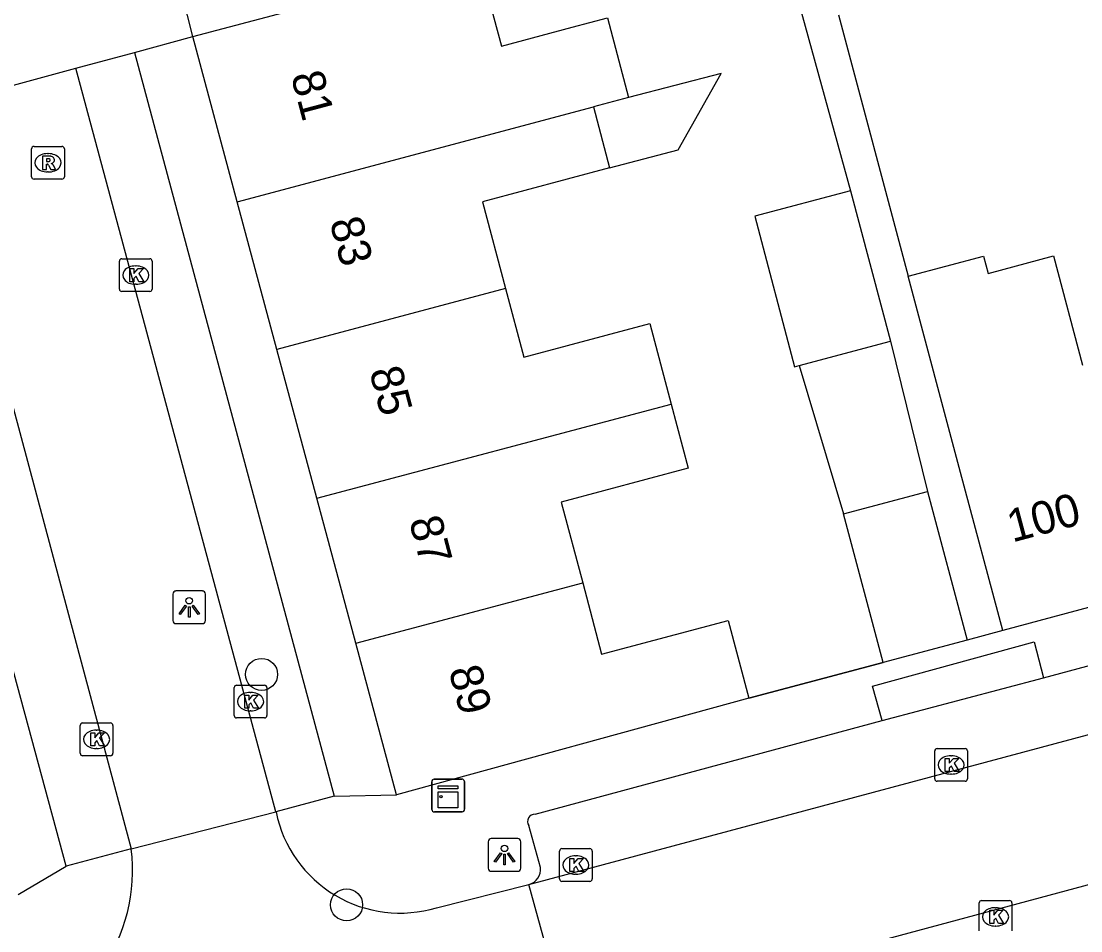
# Model space of a CAD drawing. Extents: x 162542 to 163144, y 380786 to 381511.
# Drawn here: x 162798.21 to 162830.58, y 381069.57 to 381097.35 of the extents above; entities that cross this region are included whole.
import ezdxf

# ---------------------------------------------------------------- set-up
doc = ezdxf.new("R2010")
doc.units = 0
for name, color, linetype in [('IMGEO_Boom', 7, 'Continuous'), ('IMGEO_Kast', 7, 'Continuous'), ('IMGEO_Kolk', 7, 'Continuous'), ('IMGEO_Lichtpunt', 7, 'Continuous'), ('IMGEO_Muur', 7, 'Continuous'), ('IMGEO_Pand', 7, 'Continuous'), ('IMGEO_Pand_nummerreeks', 7, 'Continuous'), ('IMGEO_Rijbaan_lokaal_open', 7, 'Continuous'), ('IMGEO_Rioolput', 7, 'Continuous'), ('IMGEO_Voetpad_open', 7, 'Continuous')]:
    doc.layers.add(name, color=color, linetype=linetype)

msp = doc.modelspace()

# ---------------------------------------------------------------- linework, layer by layer
at = {"layer": 'IMGEO_Boom'}
for centre in [(162805.552, 381077.403), (162808.149, 381070.365)]:
    msp.add_circle(centre, 0.489, dxfattribs=at)
at = {"layer": 'IMGEO_Kast'}
for p, q in [((162810.751, 381073.279), (162810.751, 381074.12)), ((162810.751, 381074.12), (162810.751, 381073.279)), ((162810.826, 381074.204), (162811.667, 381074.204)), ((162811.667, 381074.204), (162810.826, 381074.204)), ((162811.751, 381074.129), (162811.751, 381073.288)), ((162811.751, 381073.288), (162811.751, 381074.129)), ((162811.676, 381073.204), (162810.835, 381073.204)), ((162810.835, 381073.204), (162811.676, 381073.204))]:
    msp.add_line(p, q, dxfattribs=at)
for points in [[(162810.946, 381073.994), (162811.546, 381073.994), (162811.546, 381073.909), (162810.946, 381073.909), (162810.946, 381073.994)], [(162810.946, 381073.819), (162811.546, 381073.819), (162811.546, 381073.33), (162810.946, 381073.33), (162810.946, 381073.819)]]:
    msp.add_lwpolyline(points, dxfattribs=at)
msp.add_circle((162811.03, 381073.668), 0.0377, dxfattribs=at)
for centre, start, end in [((162810.829, 381074.126), 92.4484, 184.2845), ((162810.829, 381074.126), 92.4484, 184.2845), ((162811.673, 381074.126), 2.4484, 94.2845), ((162811.673, 381074.126), 2.4484, 94.2845), ((162810.829, 381073.282), 182.4484, 274.2845), ((162810.829, 381073.282), 182.4484, 274.2845), ((162811.673, 381073.282), 272.4484, 4.2845), ((162811.673, 381073.282), 272.4484, 4.2845)]:
    msp.add_arc(centre, 0.0779, start, end, dxfattribs=at)
at = {"layer": 'IMGEO_Kolk'}
for p, q in [((162801.208, 381089.169), (162801.208, 381090.021)), ((162801.283, 381090.095), (162802.135, 381090.095)), ((162802.209, 381090.021), (162802.209, 381089.169)), ((162801.696, 381089.875), (162801.721, 381089.875)), ((162802.135, 381089.095), (162801.283, 381089.095)), ((162801.719, 381089.315), (162801.694, 381089.315)), ((162804.789, 381077.071), (162805.641, 381077.071)), ((162804.714, 381076.145), (162804.714, 381076.997)), ((162805.202, 381076.851), (162805.227, 381076.851)), ((162805.715, 381076.997), (162805.715, 381076.145)), ((162805.641, 381076.071), (162804.789, 381076.071)), ((162805.225, 381076.291), (162805.2, 381076.291)), ((162800.01, 381074.992), (162800.01, 381075.844)), ((162800.085, 381075.918), (162800.937, 381075.918)), ((162801.011, 381075.844), (162801.011, 381074.992)), ((162800.498, 381075.698), (162800.523, 381075.698)), ((162800.521, 381075.138), (162800.496, 381075.138)), ((162826.191, 381075.138), (162827.043, 381075.138)), ((162800.937, 381074.918), (162800.085, 381074.918)), ((162826.116, 381074.212), (162826.116, 381075.064)), ((162826.604, 381074.918), (162826.629, 381074.918)), ((162827.117, 381075.064), (162827.117, 381074.212)), ((162827.043, 381074.138), (162826.191, 381074.138)), ((162826.627, 381074.358), (162826.602, 381074.358)), ((162814.651, 381071.155), (162814.651, 381072.007)), ((162814.726, 381072.081), (162815.578, 381072.081)), ((162815.139, 381071.861), (162815.164, 381071.861)), ((162815.652, 381072.007), (162815.652, 381071.155)), ((162815.162, 381071.301), (162815.137, 381071.301)), ((162815.578, 381071.081), (162814.726, 381071.081)), ((162827.473, 381069.572), (162827.473, 381070.424)), ((162827.548, 381070.498), (162828.4, 381070.498)), ((162827.961, 381070.278), (162827.986, 381070.278)), ((162828.474, 381070.424), (162828.474, 381069.572)), ((162827.984, 381069.718), (162827.959, 381069.718))]:
    msp.add_line(p, q, dxfattribs=at)
for points in [[(162801.208, 381089.169), (162801.208, 381090.021)], [(162801.283, 381090.095), (162802.135, 381090.095)], [(162802.209, 381090.021), (162802.209, 381089.169)], [(162801.529, 381089.795), (162801.652, 381089.795), (162801.652, 381089.644), (162801.782, 381089.795), (162801.946, 381089.795), (162801.8, 381089.644), (162801.953, 381089.395), (162801.801, 381089.395), (162801.716, 381089.559), (162801.652, 381089.492), (162801.652, 381089.395), (162801.529, 381089.395), (162801.529, 381089.795)], [(162802.135, 381089.095), (162801.283, 381089.095)], [(162804.789, 381077.071), (162805.641, 381077.071)], [(162804.714, 381076.145), (162804.714, 381076.997)], [(162805.035, 381076.771), (162805.158, 381076.771), (162805.158, 381076.62), (162805.288, 381076.771), (162805.452, 381076.771), (162805.306, 381076.62), (162805.459, 381076.371), (162805.307, 381076.371), (162805.222, 381076.535), (162805.158, 381076.468), (162805.158, 381076.371), (162805.035, 381076.371), (162805.035, 381076.771)], [(162805.715, 381076.997), (162805.715, 381076.145)], [(162805.641, 381076.071), (162804.789, 381076.071)], [(162800.01, 381074.992), (162800.01, 381075.844)], [(162800.085, 381075.918), (162800.937, 381075.918)], [(162801.011, 381075.844), (162801.011, 381074.992)], [(162800.331, 381075.618), (162800.454, 381075.618), (162800.454, 381075.467), (162800.584, 381075.618), (162800.748, 381075.618), (162800.602, 381075.467), (162800.755, 381075.218), (162800.603, 381075.218), (162800.518, 381075.382), (162800.454, 381075.315), (162800.454, 381075.218), (162800.331, 381075.218), (162800.331, 381075.618)], [(162826.191, 381075.138), (162827.043, 381075.138)], [(162800.937, 381074.918), (162800.085, 381074.918)], [(162826.116, 381074.212), (162826.116, 381075.064)], [(162826.437, 381074.838), (162826.56, 381074.838), (162826.56, 381074.687), (162826.69, 381074.838), (162826.854, 381074.838), (162826.708, 381074.687), (162826.861, 381074.438), (162826.709, 381074.438), (162826.624, 381074.602), (162826.56, 381074.535), (162826.56, 381074.438), (162826.437, 381074.438), (162826.437, 381074.838)], [(162827.117, 381075.064), (162827.117, 381074.212)], [(162827.043, 381074.138), (162826.191, 381074.138)], [(162814.651, 381071.155), (162814.651, 381072.007)], [(162814.726, 381072.081), (162815.578, 381072.081)], [(162815.652, 381072.007), (162815.652, 381071.155)], [(162814.972, 381071.781), (162815.095, 381071.781), (162815.095, 381071.63), (162815.225, 381071.781), (162815.389, 381071.781), (162815.243, 381071.63), (162815.396, 381071.381), (162815.244, 381071.381), (162815.159, 381071.545), (162815.095, 381071.478), (162815.095, 381071.381), (162814.972, 381071.381), (162814.972, 381071.781)], [(162815.578, 381071.081), (162814.726, 381071.081)], [(162827.473, 381069.572), (162827.473, 381070.424)], [(162827.548, 381070.498), (162828.4, 381070.498)], [(162828.474, 381070.424), (162828.474, 381069.572)], [(162827.794, 381070.198), (162827.917, 381070.198), (162827.917, 381070.047), (162828.047, 381070.198), (162828.211, 381070.198), (162828.065, 381070.047), (162828.218, 381069.798), (162828.066, 381069.798), (162827.981, 381069.962), (162827.917, 381069.895), (162827.917, 381069.798), (162827.794, 381069.798), (162827.794, 381070.198)]]:
    msp.add_lwpolyline(points, dxfattribs=at)
for centre, start, end in [((162801.285, 381090.019), 91.552, 178.448), ((162801.285, 381090.019), 91.552, 178.448), ((162802.133, 381090.019), 1.552, 88.448), ((162802.133, 381090.019), 1.552, 88.448), ((162801.285, 381089.171), 181.552, 268.448), ((162801.285, 381089.171), 181.552, 268.448), ((162802.133, 381089.171), 271.552, 358.448), ((162802.133, 381089.171), 271.552, 358.448), ((162804.791, 381076.995), 91.552, 178.448), ((162804.791, 381076.995), 91.552, 178.448), ((162805.639, 381076.995), 1.552, 88.448), ((162805.639, 381076.995), 1.552, 88.448), ((162804.791, 381076.147), 181.552, 268.448), ((162804.791, 381076.147), 181.552, 268.448), ((162805.639, 381076.147), 271.552, 358.448), ((162805.639, 381076.147), 271.552, 358.448), ((162800.087, 381075.842), 91.552, 178.448), ((162800.087, 381075.842), 91.552, 178.448), ((162800.935, 381075.842), 1.552, 88.448), ((162800.935, 381075.842), 1.552, 88.448), ((162826.193, 381075.062), 91.552, 178.448), ((162826.193, 381075.062), 91.552, 178.448), ((162827.041, 381075.062), 1.552, 88.448), ((162827.041, 381075.062), 1.552, 88.448), ((162800.087, 381074.994), 181.552, 268.448), ((162800.087, 381074.994), 181.552, 268.448), ((162800.935, 381074.994), 271.552, 358.448), ((162800.935, 381074.994), 271.552, 358.448), ((162826.193, 381074.214), 181.552, 268.448), ((162826.193, 381074.214), 181.552, 268.448), ((162827.041, 381074.214), 271.552, 358.448), ((162827.041, 381074.214), 271.552, 358.448), ((162814.728, 381072.005), 91.552, 178.448), ((162814.728, 381072.005), 91.552, 178.448), ((162815.576, 381072.005), 1.552, 88.448), ((162815.576, 381072.005), 1.552, 88.448), ((162814.728, 381071.157), 181.552, 268.448), ((162814.728, 381071.157), 181.552, 268.448), ((162815.576, 381071.157), 271.552, 358.448), ((162815.576, 381071.157), 271.552, 358.448), ((162827.55, 381070.422), 91.552, 178.448), ((162827.55, 381070.422), 91.552, 178.448), ((162828.398, 381070.422), 1.552, 88.448), ((162828.398, 381070.422), 1.552, 88.448)]:
    msp.add_arc(centre, 0.0765, start, end, dxfattribs=at)
for centre, major_axis, ratio, start_param, end_param in [((162801.695, 381089.595), (-0.387, 0.002), 0.722429, 4.712389, 7.853982), ((162801.72, 381089.595), (-0.39, 0.002), 0.717154, 1.570796, 4.712389), ((162805.201, 381076.571), (-0.387, 0.002), 0.722429, 4.712389, 7.853982), ((162805.226, 381076.571), (-0.39, 0.002), 0.717154, 1.570796, 4.712389), ((162800.497, 381075.418), (-0.387, 0.002), 0.722429, 4.712389, 7.853982), ((162800.522, 381075.418), (-0.39, 0.002), 0.717154, 1.570796, 4.712389), ((162826.603, 381074.638), (-0.387, 0.002), 0.722429, 4.712389, 7.853982), ((162826.628, 381074.638), (-0.39, 0.002), 0.717154, 1.570796, 4.712389), ((162815.138, 381071.581), (-0.387, 0.002), 0.722429, 4.712389, 7.853982), ((162815.163, 381071.581), (-0.39, 0.002), 0.717154, 1.570796, 4.712389), ((162827.96, 381069.998), (-0.387, 0.002), 0.722429, 4.712389, 7.853982), ((162827.985, 381069.998), (-0.39, 0.002), 0.717154, 1.570796, 4.712389)]:
    msp.add_ellipse(centre, major_axis=major_axis, ratio=ratio, start_param=start_param, end_param=end_param, dxfattribs=at)
at = {"layer": 'IMGEO_Lichtpunt'}
for p, q in [((162803.744, 381079.949), (162802.936, 381079.949)), ((162803.744, 381079.949), (162802.936, 381079.949)), ((162802.842, 381079.854), (162802.842, 381079.047)), ((162802.842, 381079.854), (162802.842, 381079.047)), ((162803.838, 381079.047), (162803.838, 381079.854)), ((162803.838, 381079.047), (162803.838, 381079.854)), ((162802.936, 381078.953), (162803.744, 381078.953)), ((162802.936, 381078.953), (162803.744, 381078.953)), ((162812.475, 381072.292), (162812.475, 381071.485)), ((162812.475, 381072.292), (162812.475, 381071.485)), ((162813.377, 381072.387), (162812.569, 381072.387)), ((162813.377, 381072.387), (162812.569, 381072.387)), ((162813.471, 381071.485), (162813.471, 381072.292)), ((162813.471, 381071.485), (162813.471, 381072.292)), ((162812.569, 381071.391), (162813.377, 381071.391)), ((162812.569, 381071.391), (162813.377, 381071.391))]:
    msp.add_line(p, q, dxfattribs=at)
for points in [[(162803.216, 381079.518), (162803.255, 381079.49), (162803.067, 381079.228), (162803.029, 381079.255), (162803.216, 381079.518)], [(162803.318, 381079.47), (162803.365, 381079.47), (162803.365, 381079.148), (162803.318, 381079.148), (162803.318, 381079.47)], [(162803.428, 381079.49), (162803.466, 381079.517), (162803.653, 381079.255), (162803.614, 381079.227), (162803.428, 381079.49)], [(162812.849, 381071.956), (162812.888, 381071.928), (162812.7, 381071.666), (162812.662, 381071.693), (162812.849, 381071.956)], [(162812.951, 381071.908), (162812.998, 381071.908), (162812.998, 381071.586), (162812.951, 381071.586), (162812.951, 381071.908)], [(162813.061, 381071.928), (162813.099, 381071.955), (162813.286, 381071.693), (162813.247, 381071.665), (162813.061, 381071.928)]]:
    msp.add_lwpolyline(points, dxfattribs=at)
for centre in [(162803.341, 381079.652), (162812.974, 381072.09)]:
    msp.add_circle(centre, 0.0994, dxfattribs=at)
for centre, start, end in [((162802.936, 381079.854), 90, 180), ((162802.936, 381079.854), 90, 180), ((162803.744, 381079.854), 0, 90), ((162803.744, 381079.854), 0, 90), ((162802.936, 381079.047), 180, 270), ((162802.936, 381079.047), 180, 270), ((162803.744, 381079.047), 270, 0), ((162803.744, 381079.047), 270, 360), ((162812.569, 381072.292), 90, 180), ((162812.569, 381072.292), 90, 180), ((162813.377, 381072.292), 0, 90), ((162813.377, 381072.292), 0, 90), ((162812.569, 381071.485), 180, 270), ((162812.569, 381071.485), 180, 270), ((162813.377, 381071.485), 270, 0), ((162813.377, 381071.485), 270, 360)]:
    msp.add_arc(centre, 0.0946, start, end, dxfattribs=at)
at = {"layer": 'IMGEO_Muur'}
msp.add_lwpolyline([(162820.439, 381076.677), (162824.537, 381077.766)], dxfattribs=at)
at = {"layer": 'IMGEO_Pand'}
for points in [[(162803.453, 381096.881), (162812.174, 381099.193)], [(162812.174, 381099.193), (162812.876, 381096.59), (162815.043, 381097.166), (162816.119, 381097.452), (162816.765, 381095.021)], [(162804.809, 381091.832), (162803.453, 381096.881)], [(162816.185, 381092.867), (162818.283, 381093.424), (162819.596, 381095.751), (162816.765, 381095.021)], [(162816.765, 381095.021), (162815.689, 381094.735)], [(162804.809, 381091.832), (162815.689, 381094.735)], [(162815.689, 381094.735), (162816.185, 381092.867)], [(162816.185, 381092.867), (162812.304, 381091.837), (162813.008, 381089.186)], [(162823.546, 381092.17), (162820.616, 381091.392), (162821.834, 381086.799), (162821.973, 381086.836)], [(162823.546, 381092.17), (162824.764, 381087.576)], [(162806.02, 381087.321), (162804.809, 381091.832)], [(162825.305, 381089.562), (162827.605, 381090.177), (162827.746, 381089.648), (162829.739, 381090.18), (162830.63, 381086.845)], [(162828.195, 381078.741), (162826.905, 381083.572), (162825.305, 381089.562)], [(162813.008, 381089.186), (162806.02, 381087.321)], [(162813.008, 381089.186), (162813.563, 381087.093), (162817.409, 381088.114), (162818.062, 381085.655)], [(162821.973, 381086.836), (162824.764, 381087.576)], [(162824.764, 381087.576), (162825.896, 381082.991)], [(162807.239, 381082.782), (162806.02, 381087.321)], [(162821.973, 381086.836), (162823.33, 381082.31)], [(162807.239, 381082.782), (162818.062, 381085.655)], [(162818.062, 381085.655), (162818.582, 381083.695), (162814.706, 381082.666), (162815.362, 381080.195)], [(162823.33, 381082.31), (162825.896, 381082.991)], [(162825.896, 381082.991), (162827.103, 381078.447)], [(162808.428, 381078.354), (162807.239, 381082.782)], [(162824.537, 381077.766), (162823.33, 381082.31)], [(162808.428, 381078.354), (162815.362, 381080.195)], [(162815.362, 381080.195), (162815.94, 381078.019), (162819.81, 381079.046), (162820.439, 381076.677)], [(162832.488, 381079.888), (162828.195, 381078.741)], [(162809.671, 381073.727), (162808.428, 381078.354)], [(162827.103, 381078.447), (162824.537, 381077.766)], [(162820.439, 381076.677), (162809.671, 381073.727)]]:
    msp.add_lwpolyline(points, dxfattribs=at)
at = {"layer": 'IMGEO_Rijbaan_lokaal_open'}
for points in [[(162803.453, 381096.881), (162802.147, 381102.023)], [(162801.665, 381096.397), (162803.453, 381096.881)], [(162799.877, 381095.912), (162801.665, 381096.397)], [(162795.495, 381094.724), (162799.877, 381095.912)], [(162805.992, 381073.201), (162799.877, 381095.912)], [(162795.495, 381094.724), (162801.57, 381072.075)], [(162813.721, 381070.983), (162851.581, 381081.128)], [(162851.855, 381076.637), (162815.604, 381066.881)], [(162801.57, 381072.075), (162805.992, 381073.201)], [(162810.899, 381070.277), (162813.721, 381070.983)], [(162814.901, 381066.703), (162813.721, 381070.983)]]:
    msp.add_lwpolyline(points, dxfattribs=at)
for centre, radius, start, end in [((162809.781, 381073.98), 3.868, 191.6144, 286.8056), ((162796.373, 381071.413), 5.239, 282.7716, 7.263)]:
    msp.add_arc(centre, radius, start, end, dxfattribs=at)
at = {"layer": 'IMGEO_Rioolput'}
for p, q in [((162798.525, 381092.599), (162798.525, 381093.451)), ((162798.6, 381093.525), (162799.452, 381093.525)), ((162799.013, 381093.305), (162799.038, 381093.305)), ((162799.526, 381093.451), (162799.526, 381092.599)), ((162799.036, 381092.745), (162799.011, 381092.745)), ((162799.452, 381092.525), (162798.6, 381092.525))]:
    msp.add_line(p, q, dxfattribs=at)
for points in [[(162798.525, 381092.599), (162798.525, 381093.451)], [(162798.6, 381093.525), (162799.452, 381093.525)], [(162799.114, 381093.223), (162798.862, 381093.225), (162798.862, 381092.825)], [(162799.526, 381093.451), (162799.526, 381092.599)], [(162798.862, 381092.825), (162798.986, 381092.825), (162798.986, 381092.987), (162798.997, 381092.987)], [(162799.04, 381093.144), (162798.986, 381093.144), (162798.986, 381093.063)], [(162798.986, 381093.063), (162799.038, 381093.063)], [(162799.044, 381092.958), (162799.115, 381092.825), (162799.255, 381092.825), (162799.19, 381092.951)], [(162799.452, 381092.525), (162798.6, 381092.525)]]:
    msp.add_lwpolyline(points, dxfattribs=at)
for centre, radius, start, end in [((162798.602, 381093.449), 0.0765, 91.552, 178.448), ((162798.602, 381093.449), 0.0765, 91.552, 178.448), ((162799.113, 381093.113), 0.109, 350.3612, 89.416), ((162799.45, 381093.449), 0.0765, 1.552, 88.448), ((162799.45, 381093.449), 0.0765, 1.552, 88.448), ((162798.996, 381092.934), 0.0533, 26.0293, 88.6989), ((162799.022, 381093.252), 0.19, 274.7715, 282.9687), ((162799.046, 381093.048), 0.0964, 77.0061, 93.1865), ((162799.06, 381093.105), 0.0378, 276.6634, 79.6772), ((162799.111, 381093.113), 0.112, 277.5842, 350.9817), ((162799.095, 381092.898), 0.108, 29.5134, 73.7905), ((162798.602, 381092.601), 0.0765, 181.552, 268.448), ((162798.602, 381092.601), 0.0765, 181.552, 268.448), ((162799.45, 381092.601), 0.0765, 271.552, 358.448), ((162799.45, 381092.601), 0.0765, 271.552, 358.448)]:
    msp.add_arc(centre, radius, start, end, dxfattribs=at)
for centre, major_axis, ratio, start_param, end_param in [((162799.012, 381093.025), (-0.387, 0.002), 0.722429, 4.712389, 7.853982), ((162799.037, 381093.025), (-0.39, 0.002), 0.717154, 1.570796, 4.712389)]:
    msp.add_ellipse(centre, major_axis=major_axis, ratio=ratio, start_param=start_param, end_param=end_param, dxfattribs=at)
at = {"layer": 'IMGEO_Voetpad_open'}
for points in [[(162829.44, 381077.293), (162857.097, 381084.74), (162857.529, 381083.089), (162861.656, 381084.179), (162861.251, 381085.851), (162866.655, 381087.296), (162874.876, 381089.481), (162907.148, 381098.095), (162922.391, 381102.163), (162922.875, 381100.201)], [(162820.968, 381101.532), (162823.546, 381092.17)], [(162823.171, 381097.541), (162825.305, 381089.562)], [(162801.665, 381096.397), (162807.774, 381073.68)], [(162799.581, 381071.542), (162793.451, 381094.17)], [(162828.195, 381078.741), (162827.103, 381078.447)], [(162824.507, 381075.999), (162824.218, 381077.039), (162829.156, 381078.395), (162829.44, 381077.293)], [(162824.537, 381077.766), (162820.439, 381076.677)], [(162824.507, 381075.999), (162829.44, 381077.293)], [(162813.905, 381073.131), (162824.507, 381075.999)], [(162807.774, 381073.68), (162805.992, 381073.201)], [(162807.774, 381073.68), (162809.671, 381073.727)], [(162814.074, 381071.504), (162813.718, 381072.785)], [(162801.57, 381072.075), (162799.581, 381071.542)], [(162798.117, 381070.679), (162799.581, 381071.542)]]:
    msp.add_lwpolyline(points, dxfattribs=at)
for centre, radius, start, end in [((162813.894, 381072.914), 0.218, 87.0116, 216.2093), ((162813.58, 381071.459), 0.496, 286.5144, 5.2469)]:
    msp.add_arc(centre, radius, start, end, dxfattribs=at)

# ---------------------------------------------------------------- texts
at = {"layer": 'IMGEO_Pand_nummerreeks'}
for s, rotation, p in [('81', 284.87, (162806.44, 381095.691)), ('83', 284.87, (162807.623, 381091.234)), ('85', 284.87, (162808.835, 381086.669)), ('100', 14.9542, (162828.486, 381081.427)), ('87', 284.87, (162810.048, 381082.103)), ('89', 284.87, (162811.26, 381077.538))]:
    msp.add_text(s, height=1, rotation=rotation, dxfattribs=at).set_placement(p)

doc.saveas('drawing.dxf')
